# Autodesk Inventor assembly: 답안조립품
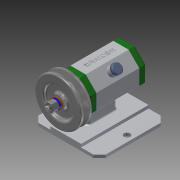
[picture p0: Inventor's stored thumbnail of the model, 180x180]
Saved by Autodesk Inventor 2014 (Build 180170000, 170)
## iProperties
Created: 2018-06
Part Number: 답안조립품
Document SubType Name: Assembly
Designer: kh
Author: kh
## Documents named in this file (16)
- C:\Users\kh\Desktop\480607V1013\답안조립품.iam
- C:\Users\kh\Desktop\480607V1013\본체.ipt
- C:\Users\kh\Desktop\480607V1013\베어링 15x32x9.ipt
- C:\Users\kh\Desktop\480607V1013\앞커버.ipt
- C:\Users\kh\Desktop\480607V1013\오일 실 15 25 7.ipt
- C:\Users\kh\Desktop\480607V1013\볼트 M4x12.ipt
- C:\Users\kh\Desktop\480607V1013\뒤커버.ipt
- C:\Users\kh\Desktop\480607V1013\고무캡.ipt
- C:\Users\kh\Desktop\480607V1013\축.ipt
- C:\Users\kh\Desktop\480607V1013\키 3x3x12.ipt
- 키 3x3x12.ipt
- C:\Users\kh\Desktop\480607V1013\V벨트풀리.ipt
- C:\Users\kh\Desktop\480607V1013\너트 M8.ipt
- 너트 M8.ipt
- C:\Users\kh\Desktop\480607V1013\스프링와셔 8.ipt
- C:\Users\kh\Desktop\480607V1013\와셔 8x17.ipt
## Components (2 placed, 2 different names)
1. 고무캡:1 — Mate:17, Mate:18, Angle:1
2. V벨트풀리:1 — Mate:24, Mate:25, Mate:27
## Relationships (6: Mate 5, Angle 1)
- Mate:17: 고무캡:1
- Mate:18: 고무캡:1
- Angle:1: 고무캡:1
- Mate:24: V벨트풀리:1
- Mate:25: V벨트풀리:1
- Mate:27: V벨트풀리:1
